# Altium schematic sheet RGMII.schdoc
size 297 x 209 mm; Symbol: Drawing-Symbol_A4; Company: 嘉立创EDA; Version: V1.0; Page Size: A4; @Project Name: 西柚在学EtherCAT; @Update Date: 2026-07-29; @Create Date: 2026-07-29; Device: Drawing-Symbol_A4; @Board Name: HPM5E3YIVK1; @Page Name: P5; @Create Time: 01:19:17; @Page Count: 5; @Page No: 5; @Schematic Name: HPM5E3YIVK1; @Update Time: 01:19:17; @Assembly Variant: Basic; Border: 1; Title Block Position: 3; Size: A4; Width: 1170; Height: 825; Region Start: 1; X Region Count: 6; Y Region Count: 4; Blade Width: 10
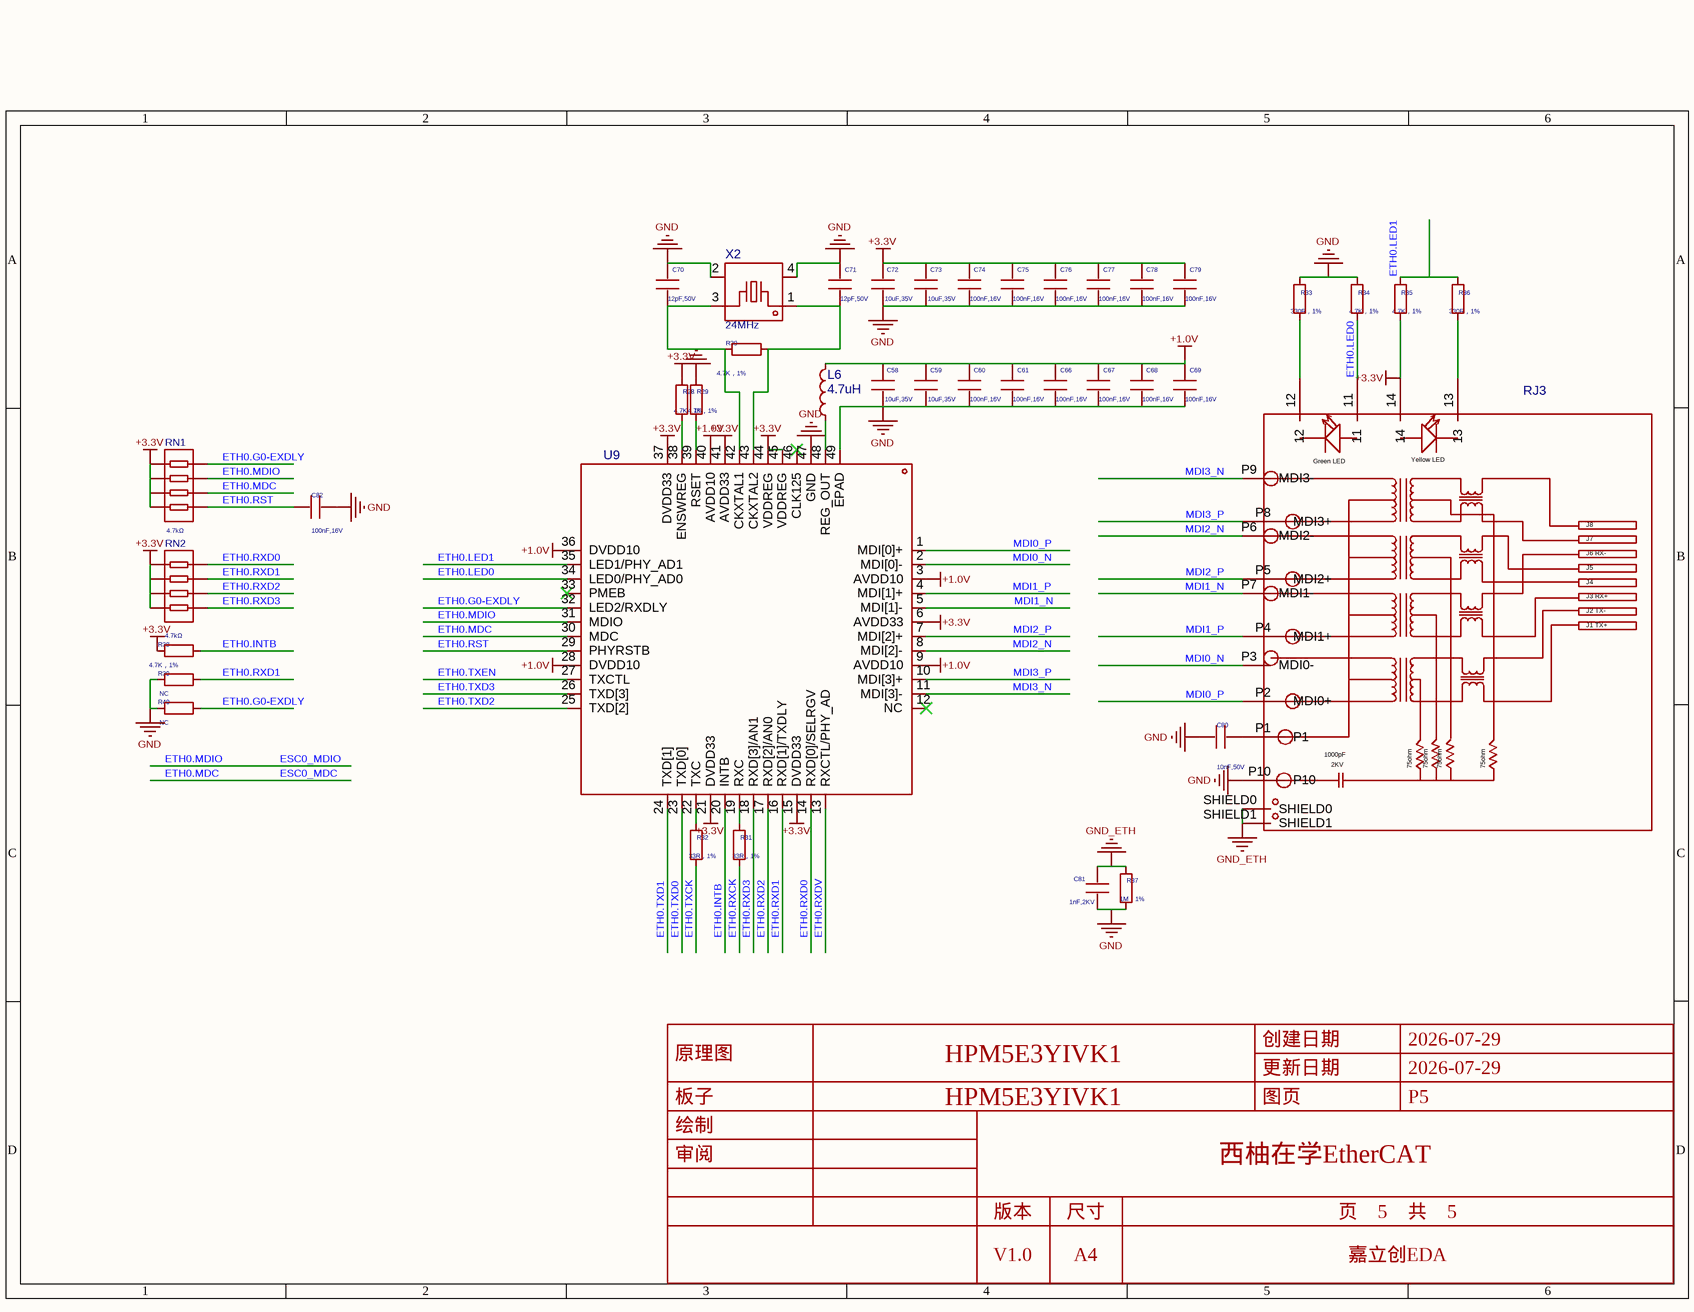
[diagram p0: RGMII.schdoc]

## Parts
C58  value 10uF,35V  [03_HPM_Capacitance:C_0603_1608Metric]
C59  value 10uF,35V  [03_HPM_Capacitance:C_0603_1608Metric]
C60  value 100nF,16V  [03_HPM_Capacitance:C_0402_1005Metric]
C61  value 100nF,16V  [03_HPM_Capacitance:C_0402_1005Metric]
C66  value 100nF,16V  [03_HPM_Capacitance:C_0402_1005Metric]
C67  value 100nF,16V  [03_HPM_Capacitance:C_0402_1005Metric]
C68  value 100nF,16V  [03_HPM_Capacitance:C_0402_1005Metric]
C69  value 100nF,16V  [03_HPM_Capacitance:C_0402_1005Metric]
C70  value 12pF,50V  [03_HPM_Capacitance:C_0402_1005Metric]
C71  value 12pF,50V  [03_HPM_Capacitance:C_0402_1005Metric]
C72  value 10uF,35V  [03_HPM_Capacitance:C_0603_1608Metric]
C73  value 10uF,35V  [03_HPM_Capacitance:C_0603_1608Metric]
C74  value 100nF,16V  [03_HPM_Capacitance:C_0402_1005Metric]
C75  value 100nF,16V  [03_HPM_Capacitance:C_0402_1005Metric]
C76  value 100nF,16V  [03_HPM_Capacitance:C_0402_1005Metric]
C77  value 100nF,16V  [03_HPM_Capacitance:C_0402_1005Metric]
C78  value 100nF,16V  [03_HPM_Capacitance:C_0402_1005Metric]
C79  value 100nF,16V  [03_HPM_Capacitance:C_0402_1005Metric]
C80  value 10nF,50V  [03_HPM_Capacitance:C_0603_1608Metric]
C81  value 1nF,2KV  [03_HPM_Capacitance:C_1206_3216Metric]
C82  value 100nF,16V  [03_HPM_Capacitance:C_0402_1005Metric]
L6  4.7uH  [IND-SMD_L2.5-W2.0-VLS252012CX-150M]
R28  value 4.7K，1%  [02_HPM_Resistor:R_0402_1005Metric]
R29  value 4.7K，1%  [02_HPM_Resistor:R_0402_1005Metric]
R30  value 4.7K，1%  [02_HPM_Resistor:R_0402_1005Metric]
R31  value 33R，1%  [02_HPM_Resistor:R_0402_1005Metric]
R32  value 33R，1%  [02_HPM_Resistor:R_0402_1005Metric]
R33  value 330R，1%  [02_HPM_Resistor:R_0402_1005Metric]
R34  value 4.7K，1%  [02_HPM_Resistor:R_0402_1005Metric]
R35  value 4.7K，1%  [02_HPM_Resistor:R_0402_1005Metric]
R36  value 330R，1%  [02_HPM_Resistor:R_0402_1005Metric]
R37  value 1M，1%  [02_HPM_Resistor:R_1206_3216Metric]
R38  value 4.7K，1%  [02_HPM_Resistor:R_0402_1005Metric]
R39  value NC  [02_HPM_Resistor:R_0402_1005Metric]
R40  value NC  [02_HPM_Resistor:R_0402_1005Metric]
RJ3  HR911130A  [RJ45-TH_HR911130A]  (value not drawn)
RN1  4.7kΩ  [RES-ARRAY-SMD_8P-L2.0-W1.0-BL_CN24XXXX]
RN2  4.7kΩ  [RES-ARRAY-SMD_8P-L2.0-W1.0-BL_CN24XXXX]
U9  RTL8211E-VB-CG  [QFN-48_L6.0-W6.0-P0.40-BL-EP3.8]  (value not drawn)
X2  24MHz  [CRYSTAL-SMD_4P-L2.0-W1.6-BL-A]

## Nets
+1.0V: C58.1 C59.1 C60.1 C61.1 C66.1 C67.1 C68.1 C69.1 L6.2 U9.3(AVDD10) U9.9(AVDD10) U9.28(DVDD10) U9.36(DVDD10) U9.40(AVDD10)
+3.3V: C72.1 C73.1 C74.1 C75.1 C76.1 C77.1 C78.1 C79.1 R28.2 R35.2 R38.2 RJ3.14 RN1.1 RN1.2 RN1.3 RN1.4 RN2.1 RN2.2 RN2.3 RN2.4 U9.6(AVDD33) U9.15(DVDD33) U9.21(DVDD33) U9.37(DVDD33) U9.41(AVDD33) U9.44(VDDREG) U9.45(VDDREG)
GND: C58.2 C59.2 C60.2 C61.2 C66.2 C67.2 C68.2 C69.2 C70.1 C71.1 C72.2 C73.2 C74.2 C75.2 C76.2 C77.2 C78.2 C79.2 C80.1 C81.2 C82.1 R29.2 R33.1 R34.1 R37.1 R39.2 R40.2 RJ3.P10 U9.47(GND) U9.49(EPAD) X2.2(GND) X2.4(GND)
GND_ETH: C81.1 R37.2 RJ3.SHIELD0 RJ3.SHIELD1
ESC0_MDC: RN1.6 U9.30(MDC)  [also labelled ETH0.MDC]
ESC0_MDIO: RN1.7 U9.31(MDIO)  [also labelled ETH0.MDIO]
ETH0.G0-EXDLY: R40.1 RN1.8 U9.32(LED2/RXDLY)
ETH0.INTB: R38.1 U9.20(INTB)
ETH0.LED0: R34.2 RJ3.11 U9.34(LED0/PHY_AD0)
ETH0.LED1: R35.1 R36.1 U9.35(LED1/PHY_AD1)
ETH0.RST: C82.2 RN1.5 U9.29(PHYRSTB)
ETH0.RXCK: R31.1
ETH0.RXD0: RN2.5 U9.14(RXD[0]/SELRGV)
ETH0.RXD1: R39.1 RN2.6 U9.16(RXD[1]/TXDLY)
ETH0.RXD2: RN2.7 U9.17(RXD[2]/AN0)
ETH0.RXD3: RN2.8 U9.18(RXD[3]/AN1)
ETH0.RXDV: U9.13(RXCTL/PHY_AD)
ETH0.TXCK: R32.1
ETH0.TXD0: U9.23(TXD[0])
ETH0.TXD1: U9.24(TXD[1])
ETH0.TXD2: U9.25(TXD[2])
ETH0.TXD3: U9.26(TXD[3])
ETH0.TXEN: U9.27(TXCTL)
MDI0_N: RJ3.P3(MDI0-) U9.2(MDI[0]-)
MDI0_P: RJ3.P2(MDI0+) U9.1(MDI[0]+)
MDI1_N: RJ3.P7(MDI1-) U9.5(MDI[1]-)
MDI1_P: RJ3.P4(MDI1+) U9.4(MDI[1]+)
MDI2_N: RJ3.P6(MDI2-) U9.8(MDI[2]-)
MDI2_P: RJ3.P5(MDI2+) U9.7(MDI[2]+)
MDI3_N: RJ3.P9(MDI3-) U9.11(MDI[3]-)
MDI3_P: RJ3.P8(MDI3+) U9.10(MDI[3]+)
NetC70_2: C70.2 R30.2 U9.42(CKXTAL1) X2.3
NetC71_2: C71.2 R30.1 U9.43(CKXTAL2) X2.1
NetC80_2: C80.2 RJ3.P1
NetL6_1: L6.1 U9.48(REG_OUT)
NetR28_1: R28.1 U9.38(ENSWREG)
NetR29_1: R29.1 U9.39(RSET)
NetR31_2: R31.2 U9.19(RXC)
NetR32_2: R32.2 U9.22(TXC)
NetR33_2: R33.2 RJ3.12
NetR36_2: R36.2 RJ3.13

Not connected (* = marked no-connect by the designer): U9 12(NC)* 33(PMEB)* 46(CLK125)*

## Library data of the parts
C58 = 电容0603: Model: CL10A226MP8NUNE; Company: SAMSUNG(三星); ki_keywords: cap capacitor; ki_description: 0603; ki_fp_filters: C_*; ID: $1I15; 3D Model: fca5be93b99f4b5a9a2fd372d58c31d90819f05c4eef4c71ace90d822a990e87; 3D Model Transform: 62.992000938653945,31.496000469326972,31.496000469326972,0,0,0,0,0,0; AddInBom: yes; UniqueId: b3e980a047527b8f_48; ModelName: C0603
C59 = 电容0603: Model: CL10A226MP8NUNE; Company: SAMSUNG(三星); ki_keywords: cap capacitor; ki_description: 0603; ki_fp_filters: C_*; ID: $1I15; 3D Model: fca5be93b99f4b5a9a2fd372d58c31d90819f05c4eef4c71ace90d822a990e87; 3D Model Transform: 62.992000938653945,31.496000469326972,31.496000469326972,0,0,0,0,0,0; AddInBom: yes; UniqueId: b3e980a047527b8f_47; ModelName: C0603
C60 = 电容0402: Model: CL05B104KO5NNNC; Company: SAMSUNG(三星); ki_keywords: cap capacitor; ki_description: 0402; ki_fp_filters: C_*; ID: $1I27; 3D Model: 222a10e09e6e477a9f85628e277082cb0819f05c4eef4c71ace90d822a990e87; 3D Model Transform: 39.37,19.685,19.685,0,0,0,0,0,0; AddInBom: yes; UniqueId: gge1051_0; ModelName: C0402
C61 = 电容0402: Model: CL05B104KO5NNNC; Company: SAMSUNG(三星); ki_keywords: cap capacitor; ki_description: 0402; ki_fp_filters: C_*; ID: $1I27; 3D Model: 222a10e09e6e477a9f85628e277082cb0819f05c4eef4c71ace90d822a990e87; 3D Model Transform: 39.37,19.685,19.685,0,0,0,0,0,0; AddInBom: yes; UniqueId: gge1051_1; ModelName: C0402
C66 = 电容0402: Model: CL05B104KO5NNNC; Company: SAMSUNG(三星); ki_keywords: cap capacitor; ki_description: 0402; ki_fp_filters: C_*; ID: $1I27; 3D Model: 222a10e09e6e477a9f85628e277082cb0819f05c4eef4c71ace90d822a990e87; 3D Model Transform: 39.37,19.685,19.685,0,0,0,0,0,0; AddInBom: yes; UniqueId: gge1051_2; ModelName: C0402
C67 = 电容0402: Model: CL05B104KO5NNNC; Company: SAMSUNG(三星); ki_keywords: cap capacitor; ki_description: 0402; ki_fp_filters: C_*; ID: $1I27; 3D Model: 222a10e09e6e477a9f85628e277082cb0819f05c4eef4c71ace90d822a990e87; 3D Model Transform: 39.37,19.685,19.685,0,0,0,0,0,0; AddInBom: yes; UniqueId: gge1051_3; ModelName: C0402
C68 = 电容0402: Model: CL05B104KO5NNNC; Company: SAMSUNG(三星); ki_keywords: cap capacitor; ki_description: 0402; ki_fp_filters: C_*; ID: $1I27; 3D Model: 222a10e09e6e477a9f85628e277082cb0819f05c4eef4c71ace90d822a990e87; 3D Model Transform: 39.37,19.685,19.685,0,0,0,0,0,0; AddInBom: yes; UniqueId: gge1051_4; ModelName: C0402
C69 = 电容0402: Model: CL05B104KO5NNNC; Company: SAMSUNG(三星); ki_keywords: cap capacitor; ki_description: 0402; ki_fp_filters: C_*; ID: $1I27; 3D Model: 222a10e09e6e477a9f85628e277082cb0819f05c4eef4c71ace90d822a990e87; 3D Model Transform: 39.37,19.685,19.685,0,0,0,0,0,0; AddInBom: yes; UniqueId: gge1051_5; ModelName: C0402
C70 = 电容0402: Model: CL05B104KO5NNNC; Company: SAMSUNG(三星); ki_keywords: cap capacitor; ki_description: 0402; ki_fp_filters: C_*; ID: $1I27; 3D Model: 222a10e09e6e477a9f85628e277082cb0819f05c4eef4c71ace90d822a990e87; 3D Model Transform: 39.37,19.685,19.685,0,0,0,0,0,0; AddInBom: yes; UniqueId: gge1051_6; ModelName: C0402
C71 = 电容0402: Model: CL05B104KO5NNNC; Company: SAMSUNG(三星); ki_keywords: cap capacitor; ki_description: 0402; ki_fp_filters: C_*; ID: $1I27; 3D Model: 222a10e09e6e477a9f85628e277082cb0819f05c4eef4c71ace90d822a990e87; 3D Model Transform: 39.37,19.685,19.685,0,0,0,0,0,0; AddInBom: yes; UniqueId: gge1051_7; ModelName: C0402
C72 = 电容0603: Model: CL10A226MP8NUNE; Company: SAMSUNG(三星); ki_keywords: cap capacitor; ki_description: 0603; ki_fp_filters: C_*; ID: $1I15; 3D Model: fca5be93b99f4b5a9a2fd372d58c31d90819f05c4eef4c71ace90d822a990e87; 3D Model Transform: 62.992000938653945,31.496000469326972,31.496000469326972,0,0,0,0,0,0; AddInBom: yes; UniqueId: b3e980a047527b8f_50; ModelName: C0603
C73 = 电容0603: Model: CL10A226MP8NUNE; Company: SAMSUNG(三星); ki_keywords: cap capacitor; ki_description: 0603; ki_fp_filters: C_*; ID: $1I15; 3D Model: fca5be93b99f4b5a9a2fd372d58c31d90819f05c4eef4c71ace90d822a990e87; 3D Model Transform: 62.992000938653945,31.496000469326972,31.496000469326972,0,0,0,0,0,0; AddInBom: yes; UniqueId: b3e980a047527b8f_49; ModelName: C0603
C74 = 电容0402: Model: CL05B104KO5NNNC; Company: SAMSUNG(三星); ki_keywords: cap capacitor; ki_description: 0402; ki_fp_filters: C_*; ID: $1I27; 3D Model: 222a10e09e6e477a9f85628e277082cb0819f05c4eef4c71ace90d822a990e87; 3D Model Transform: 39.37,19.685,19.685,0,0,0,0,0,0; AddInBom: yes; UniqueId: gge1051_8; ModelName: C0402
C75 = 电容0402: Model: CL05B104KO5NNNC; Company: SAMSUNG(三星); ki_keywords: cap capacitor; ki_description: 0402; ki_fp_filters: C_*; ID: $1I27; 3D Model: 222a10e09e6e477a9f85628e277082cb0819f05c4eef4c71ace90d822a990e87; 3D Model Transform: 39.37,19.685,19.685,0,0,0,0,0,0; AddInBom: yes; UniqueId: gge1051_9; ModelName: C0402
C76 = 电容0402: Model: CL05B104KO5NNNC; Company: SAMSUNG(三星); ki_keywords: cap capacitor; ki_description: 0402; ki_fp_filters: C_*; ID: $1I27; 3D Model: 222a10e09e6e477a9f85628e277082cb0819f05c4eef4c71ace90d822a990e87; 3D Model Transform: 39.37,19.685,19.685,0,0,0,0,0,0; AddInBom: yes; UniqueId: gge1051_10; ModelName: C0402
C77 = 电容0402: Model: CL05B104KO5NNNC; Company: SAMSUNG(三星); ki_keywords: cap capacitor; ki_description: 0402; ki_fp_filters: C_*; ID: $1I27; 3D Model: 222a10e09e6e477a9f85628e277082cb0819f05c4eef4c71ace90d822a990e87; 3D Model Transform: 39.37,19.685,19.685,0,0,0,0,0,0; AddInBom: yes; UniqueId: gge1051_11; ModelName: C0402
C78 = 电容0402: Model: CL05B104KO5NNNC; Company: SAMSUNG(三星); ki_keywords: cap capacitor; ki_description: 0402; ki_fp_filters: C_*; ID: $1I27; 3D Model: 222a10e09e6e477a9f85628e277082cb0819f05c4eef4c71ace90d822a990e87; 3D Model Transform: 39.37,19.685,19.685,0,0,0,0,0,0; AddInBom: yes; UniqueId: gge1051_12; ModelName: C0402
C79 = 电容0402: Model: CL05B104KO5NNNC; Company: SAMSUNG(三星); ki_keywords: cap capacitor; ki_description: 0402; ki_fp_filters: C_*; ID: $1I27; 3D Model: 222a10e09e6e477a9f85628e277082cb0819f05c4eef4c71ace90d822a990e87; 3D Model Transform: 39.37,19.685,19.685,0,0,0,0,0,0; AddInBom: yes; UniqueId: gge1051_13; ModelName: C0402
C80 = 电容0603: Model: CL10A226MP8NUNE; Company: SAMSUNG(三星); ki_keywords: cap capacitor; ki_description: 0603; ki_fp_filters: C_*; ID: $1I15; 3D Model: fca5be93b99f4b5a9a2fd372d58c31d90819f05c4eef4c71ace90d822a990e87; 3D Model Transform: 62.992000938653945,31.496000469326972,31.496000469326972,0,0,0,0,0,0; AddInBom: yes; UniqueId: b3e980a047527b8f_51; ModelName: C0603
C81 = 电容1206: Model: 1206B102K202NT; Company: FH(风华); ki_keywords: cap capacitor; ki_description: 1206; ki_fp_filters: C_*; ID: $4I70; 3D Model: e4be705b945545a48e666415e3682bd80819f05c4eef4c71ace90d822a990e87; 3D Model Transform: 125.98400187730789,62.992000938653945,51.1809981226921,0,0,0,0,0,0; AddInBom: yes; UniqueId: gge1035_0; ModelName: C1206_L3.2-W1.6-H1.3
C82 = 电容0402: Model: CL05B104KO5NNNC; Company: SAMSUNG(三星); ki_keywords: cap capacitor; ki_description: 0402; ki_fp_filters: C_*; ID: $1I27; 3D Model: 222a10e09e6e477a9f85628e277082cb0819f05c4eef4c71ace90d822a990e87; 3D Model Transform: 39.37,19.685,19.685,0,0,0,0,0,0; AddInBom: yes; UniqueId: gge1051_14; ModelName: C0402
L6 = FTC252010S4R7MBCA: Manufacturer: cjiang(长江微电); Tolerance: ±20%; Rated Current: 2A; Saturation Current (Isat): 2.6A; DC Resistance (DCR): 160mΩ; Type: 一体成型电感; 3D Model: e143e04106934774881cec608355723f; 3D Model Transform: 98.504,78.819,0,0,0,0,-0.004,-0.003,0; AddInBom: yes
R28 = 电阻0402: Model: 0402WGF1002TCE; Company: UNI-ROYAL(厚声); ki_keywords: R res resistor; ki_description: Resistor; ki_fp_filters: R_*; ID: $3I57; 3D Model: 98c88bc2b9094f218f3a3e30a70127380819f05c4eef4c71ace90d822a990e87; 3D Model Transform: 39.37,19.685,14.173200563192367,0,0,0,0,0,0; AddInBom: yes; UniqueId: 469542c170a520e3_9; ModelName: R0402_L1.0-W0.5-H0.4
R29 = 电阻0402: Model: 0402WGF1002TCE; Company: UNI-ROYAL(厚声); ki_keywords: R res resistor; ki_description: Resistor; ki_fp_filters: R_*; ID: $3I57; 3D Model: 98c88bc2b9094f218f3a3e30a70127380819f05c4eef4c71ace90d822a990e87; 3D Model Transform: 39.37,19.685,14.173200563192367,0,0,0,0,0,0; AddInBom: yes; UniqueId: 469542c170a520e3_10; ModelName: R0402_L1.0-W0.5-H0.4
R30 = 电阻0402: Model: 0402WGF1002TCE; Company: UNI-ROYAL(厚声); ki_keywords: R res resistor; ki_description: Resistor; ki_fp_filters: R_*; ID: $3I57; 3D Model: 98c88bc2b9094f218f3a3e30a70127380819f05c4eef4c71ace90d822a990e87; 3D Model Transform: 39.37,19.685,14.173200563192367,0,0,0,0,0,0; AddInBom: yes; UniqueId: 469542c170a520e3_11; ModelName: R0402_L1.0-W0.5-H0.4
R31 = 电阻0402: Model: 0402WGF1002TCE; Company: UNI-ROYAL(厚声); ki_keywords: R res resistor; ki_description: Resistor; ki_fp_filters: R_*; ID: $3I57; 3D Model: 98c88bc2b9094f218f3a3e30a70127380819f05c4eef4c71ace90d822a990e87; 3D Model Transform: 39.37,19.685,14.173200563192367,0,0,0,0,0,0; AddInBom: yes; UniqueId: 469542c170a520e3_12; ModelName: R0402_L1.0-W0.5-H0.4
R32 = 电阻0402: Model: 0402WGF1002TCE; Company: UNI-ROYAL(厚声); ki_keywords: R res resistor; ki_description: Resistor; ki_fp_filters: R_*; ID: $3I57; 3D Model: 98c88bc2b9094f218f3a3e30a70127380819f05c4eef4c71ace90d822a990e87; 3D Model Transform: 39.37,19.685,14.173200563192367,0,0,0,0,0,0; AddInBom: yes; UniqueId: 469542c170a520e3_13; ModelName: R0402_L1.0-W0.5-H0.4
R33 = 电阻0402: Model: 0402WGF1002TCE; Company: UNI-ROYAL(厚声); ki_keywords: R res resistor; ki_description: Resistor; ki_fp_filters: R_*; ID: $3I57; 3D Model: 98c88bc2b9094f218f3a3e30a70127380819f05c4eef4c71ace90d822a990e87; 3D Model Transform: 39.37,19.685,14.173200563192367,0,0,0,0,0,0; AddInBom: yes; UniqueId: 469542c170a520e3_14; ModelName: R0402_L1.0-W0.5-H0.4
R34 = 电阻0402: Model: 0402WGF1002TCE; Company: UNI-ROYAL(厚声); ki_keywords: R res resistor; ki_description: Resistor; ki_fp_filters: R_*; ID: $3I57; 3D Model: 98c88bc2b9094f218f3a3e30a70127380819f05c4eef4c71ace90d822a990e87; 3D Model Transform: 39.37,19.685,14.173200563192367,0,0,0,0,0,0; AddInBom: yes; UniqueId: 469542c170a520e3_15; ModelName: R0402_L1.0-W0.5-H0.4
R35 = 电阻0402: Model: 0402WGF1002TCE; Company: UNI-ROYAL(厚声); ki_keywords: R res resistor; ki_description: Resistor; ki_fp_filters: R_*; ID: $3I57; 3D Model: 98c88bc2b9094f218f3a3e30a70127380819f05c4eef4c71ace90d822a990e87; 3D Model Transform: 39.37,19.685,14.173200563192367,0,0,0,0,0,0; AddInBom: yes; UniqueId: 469542c170a520e3_16; ModelName: R0402_L1.0-W0.5-H0.4
R36 = 电阻0402: Model: 0402WGF1002TCE; Company: UNI-ROYAL(厚声); ki_keywords: R res resistor; ki_description: Resistor; ki_fp_filters: R_*; ID: $3I57; 3D Model: 98c88bc2b9094f218f3a3e30a70127380819f05c4eef4c71ace90d822a990e87; 3D Model Transform: 39.37,19.685,14.173200563192367,0,0,0,0,0,0; AddInBom: yes; UniqueId: 469542c170a520e3_17; ModelName: R0402_L1.0-W0.5-H0.4
R37 = 电阻1206: Model: ARG06BTC1004; Company: Viking(光颉); ki_keywords: R res resistor; ki_description: Resistor; ki_fp_filters: R_*; ID: $4I74; 3D Model: 89a1f13db2384da588040e0b3c55bf660819f05c4eef4c71ace90d822a990e87; 3D Model Transform: 125.98400187730789,62.992000938653945,22.047200093865392,0,0,0,0,0,0; AddInBom: yes; UniqueId: gge1033_0; ModelName: R1206_L3.2-W1.6-H0.6
R38 = 电阻0402: Model: 0402WGF1002TCE; Company: UNI-ROYAL(厚声); ki_keywords: R res resistor; ki_description: Resistor; ki_fp_filters: R_*; ID: $3I57; 3D Model: 98c88bc2b9094f218f3a3e30a70127380819f05c4eef4c71ace90d822a990e87; 3D Model Transform: 39.37,19.685,14.173200563192367,0,0,0,0,0,0; AddInBom: yes; UniqueId: 469542c170a520e3_18; ModelName: R0402_L1.0-W0.5-H0.4
R39 = 电阻0402: Model: 0402WGF1002TCE; Company: UNI-ROYAL(厚声); ki_keywords: R res resistor; ki_description: Resistor; ki_fp_filters: R_*; ID: $3I57; 3D Model: 98c88bc2b9094f218f3a3e30a70127380819f05c4eef4c71ace90d822a990e87; 3D Model Transform: 39.37,19.685,14.173200563192367,0,0,0,0,0,0; Add into BOM: no; ConvertToPcb: yes; UniqueId: 469542c170a520e3_19; ModelName: R0402_L1.0-W0.5-H0.4
R40 = 电阻0402: Model: 0402WGF1002TCE; Company: UNI-ROYAL(厚声); ki_keywords: R res resistor; ki_description: Resistor; ki_fp_filters: R_*; ID: $3I57; 3D Model: 98c88bc2b9094f218f3a3e30a70127380819f05c4eef4c71ace90d822a990e87; 3D Model Transform: 39.37,19.685,14.173200563192367,0,0,0,0,0,0; Add into BOM: no; ConvertToPcb: yes; UniqueId: 469542c170a520e3_20; ModelName: R0402_L1.0-W0.5-H0.4
RJ3 = HR911130A: Manufacturer: HANRUN(汉仁); Connector Type: RJ45插座; Number of Ports: 1; LED: 带LED; 3D Model: 21112b2bcfef4316930bd636ff253b92; 3D Model Transform: 635.432,838.62,0,180,0,0,0,88.937,-157.48; AddInBom: yes
RN1 RN2 = 4D02WGF0000TCE: 电阻器数:4;阻值:0Ω;精度:±1%;单个元件功率:62.5mW;温度系数:±200ppm/℃;; Manufacturer: UNI-ROYAL(厚声); 3D Model: 572b8be1149d40328062c4dbb13b26790819f05c4eef4c71ace90d822a990e87; 3D Model Transform: 78.74,43.307,0,0,0,0,-0.001,-0.002,0; Number of Resistors: 4; Tolerance: ±1%; Power(Watts): 62.5mW; AddInBom: yes; ModelName: RES-ARRAY-SMD_8P-L2.0-W1.0-BL-1
U9 = RTL8211E-VB-CG: Manufacturer: REALTEK(瑞昱); Application Function: PHY收发器; Number of Channels: 4; Interface: RGMII；GMII; Supply Voltage: 3.3V；1.8V；2.5V；1.5V; 3D Model: 3abfe16d41e74c4a923f5a79948fd36c; 3D Model Transform: 237.007,237.007,0,0,0,0,0,0,0; AddInBom: yes
X2 = 晶振2016: Manufacturer: YXC(扬兴晶振); ManufacturerPart: XL7EL89CKI-111YLC-24M; Normal temperature Frequency Tolerance: ±10ppm; Load Capacitance: 8pF; Frequency Stability: ±20ppm; AddInBom: yes; UniqueId: gge1091; ID: $1I86; ModelId: 3c7217722bdc4daeae1fd6f7f164cfcf0819f05c4eef4c71ace90d822a990e87; ModelName: CRYSTAL-SMD_4P-L2.0-W1.6-BL-2; ModelTransform: 78.74,62.992000938653945,18.110199521873145,0,0,0,0,0,0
